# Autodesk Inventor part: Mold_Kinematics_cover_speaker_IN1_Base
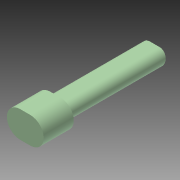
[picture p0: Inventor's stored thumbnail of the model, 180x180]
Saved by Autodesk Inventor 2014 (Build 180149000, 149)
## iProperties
Created: 2009-12
Part Number: Mold_Kinematics_cover_speaker_IN1_Base
Document SubType Name: Modeling
Designer: gaom
Density: 1 g/cm^3
Material: Generic
Appearance: Green Pastel
Author: gaom
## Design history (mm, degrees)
feature "Surface1"
feature "Surface2"
feature "OffsetSrf1" dims "d0" = 0
feature "OffsetSrf5" dims "d4" = 0
feature "OffsetSrf4" dims "d3" = 0
feature "OffsetSrf3" dims "d2" = 0
feature "OffsetSrf2" dims "d1" = 0
feature "Stitch Surface1"
workplane "Work Plane1"
sketch "Sketch1"
  geometry: L1 (-17.008, -80.698)-(-17.008, -77.302) reference; L2 (-12.206, -77.302)-(-12.206, -80.698) reference; A1 r 2.401 centre (-14.607, -80.698) between (-17.008, -80.698) and (-12.206, -80.698) reference; A2 r 2.401 centre (-14.607, -77.302) between (-12.206, -77.302) and (-17.008, -77.302) reference
feature "Sculpt1"
sketch "Sketch2"
  geometry: L1 (3.396, 0)-(0, 0) reference; L2 (0, 4.802)-(3.396, 4.802) reference; L3 (0, -2)-(3.396, -2); L4 (3.396, 6.802)-(0, 6.802); A1 r 2.401 centre (0, 2.401) between (0, 4.802) and (0, 0) reference; A2 r 2.401 centre (3.396, 2.401) between (3.396, 0) and (3.396, 4.802) reference; A3 r 4.401 centre (0, 2.401) between (0, 6.802) and (0, -2); A4 r 4.401 centre (3.396, 2.401) between (3.396, -2) and (3.396, 6.802)
  constraints: 4 end point, 4 point on circle, 2 centre point, 3 other
  dimensions: "d8" = 2 distance between parallel lines of L4 L2
extrude "Extrusion1" join sketch "Sketch2" distance "d9" = 10; taper "d10" = 0 deg
body "Srf3"
body "Srf4"
body "Srf5"
body "Srf6"
body "Srf7"
body "Srf8"
body "Srf9"
body "Srf10"
body "Solid2"
body "Srf1"
body "Srf2"
extrude_surface "ExtrusionSrf1" dims "d5" = 0.13, "d6" = 0
patch "Boundary Patch1"
other parameters: "d7" = 0
